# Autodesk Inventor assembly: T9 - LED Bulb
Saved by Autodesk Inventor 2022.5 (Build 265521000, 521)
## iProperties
Created: 2025-02
Part Number: T9 - LED Bulb
Document SubType Name: Assembly
Designer: AdminForWorker
Title: T9 - LED Bulb
Author: AdminForWorker
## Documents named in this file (3)
- c:\worker\convert-fusion-r06-cosv3\tmp\job-1\19\temp\files\7f12bef2-acc9-47ae-8604-bbc7f61ecf5f\T9 - LED Bulb.iam
- c:\worker\convert-fusion-r06-cosv3\tmp\job-1\19\temp\files\7f12bef2-acc9-47ae-8604-bbc7f61ecf5f\T9.ipt
- c:\worker\convert-fusion-r06-cosv3\tmp\job-1\19\temp\files\7f12bef2-acc9-47ae-8604-bbc7f61ecf5f\E26 Base.ipt
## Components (2 placed, 2 different names)
1. T9:1
2. E26 Base:1
